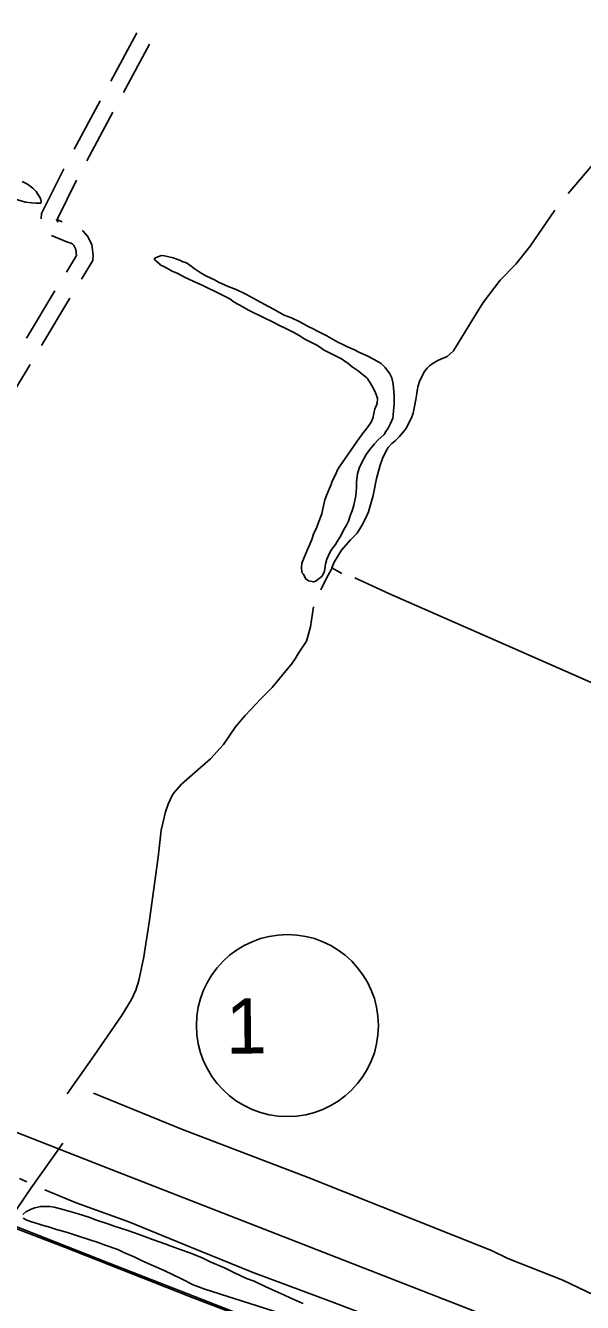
# Model space of a CAD drawing. Extents: x 3281947 to 3319794, y 715894 to 741249.
# Drawn here: x 3294621 to 3295631, y 724593 to 726907 of the extents above; entities that cross this region are included whole.
import ezdxf

# ---------------------------------------------------------------- set-up
doc = ezdxf.new("R2010")
doc.units = 0
for name, color, linetype in [('V-DTCH-CNTR', 7, 'Continuous'), ('V-RAIL-TRAK', 7, 'Continuous'), ('V-ROAD-CNTR', 7, 'Continuous'), ('V-ROAD-IDEN', 7, 'Continuous'), ('V-SITE-VEGE', 7, 'Continuous'), ('V-TOPO-SHOR', 7, 'Continuous')]:
    doc.layers.add(name, color=color, linetype=linetype)

msp = doc.modelspace()

# ---------------------------------------------------------------- linework, layer by layer
at = {"layer": 'V-DTCH-CNTR'}
msp.add_lwpolyline([(3294584.6, 724734.7), (3294604.3, 724761.8), (3294630.9, 724801.3), (3294647.3, 724824.2), (3294669.8, 724855.4), (3294688, 724881.7)], dxfattribs=at)
at = {"layer": 'V-RAIL-TRAK'}
msp.add_lwpolyline([(3295596.8, 724339.4), (3295590.1, 724342), (3295495.8, 724379), (3295404.7, 724414.1), (3295300, 724455), (3295207.5, 724491), (3295113.3, 724528.4), (3295017.6, 724565.8), (3294919.7, 724603.6), (3294791.3, 724654.3), (3294691.5, 724693.4), (3294596.8, 724729.9), (3294584.6, 724734.7)], dxfattribs=at)
at = {"layer": 'V-ROAD-CNTR'}
for p, q in [((3294775.1, 726806.1), (3294822.5, 726894.1)), ((3294798.1, 726785.6), (3294845.5, 726873.6)), ((3294708.6, 726682.9), (3294756.1, 726770.9)), ((3294731.7, 726662.3), (3294779.1, 726750.4)), ((3294622.5, 726340.4), (3294673.9, 726426.2)), ((3294649.8, 726327.6), (3294701.2, 726413.3))]:
    msp.add_line(p, q, dxfattribs=at)
for points in [[(3287528.8, 727489.4), (3288159.7, 727246.7), (3289159.6, 726857.6), (3289743.7, 726626.7), (3290210.1, 726446.4), (3290854.7, 726194.3), (3291198.3, 726062.1), (3292329.9, 725616.5), (3292874.1, 725407.4), (3293983.9, 724974.1), (3294772.1, 724664.7), (3295711.6, 724298), (3296794.9, 723876.7), (3297613.5, 723554.1), (3297991.8, 723406.1), (3298815.4, 723086.6), (3299719.3, 722731.4), (3300678.1, 722358.1)], [(3294648.8, 726557), (3294649.6, 726566.4), (3294689.9, 726647.5)], [(3294686.8, 726551.5), (3294676.5, 726555.8), (3294679, 726551.2), (3294678.5, 726553.1), (3294679, 726558.1), (3294713.2, 726626.9)], [(3294694.7, 726460.4), (3294713.2, 726490.6), (3294713.1, 726490.1), (3294711.8, 726501.6), (3294708.3, 726508.4), (3294705.8, 726511.1), (3294703.3, 726512.6), (3294697, 726514.7), (3294667.8, 726526.9)], [(3294722, 726447.5), (3294742.7, 726481.4), (3294743.2, 726491), (3294740.9, 726510.5), (3294733.1, 726525.7), (3294725, 726534.6), (3294723.4, 726535.5)], [(3294577.9, 726207.4), (3294579.7, 726210.7), (3294629.2, 726293.2)], [(3293604.8, 725293.3), (3294762.1, 724839.9), (3295753.8, 724453.1), (3296714, 724076.6), (3298094.6, 723538.7), (3299007, 723184.6), (3299321, 723061.9), (3299523.3, 722999.2), (3299701.5, 722950.5), (3299949, 722905.2), (3300134.1, 722886.4), (3300314.5, 722877.1), (3300486.9, 722878.9), (3300681.3, 722895.7), (3300871.4, 722922.7), (3301027.9, 722958.5), (3301177.9, 722998.7), (3301318.6, 723046.1), (3301415.1, 723084.5), (3301509.5, 723122.5), (3301655.6, 723193.6), (3302010.6, 723367.2), (3302498.5, 723608.3), (3302680.4, 723698.6)]]:
    msp.add_lwpolyline(points, dxfattribs=at)
at = {"layer": 'V-ROAD-IDEN'}
msp.add_circle((3295095.6, 725095), 165, dxfattribs=at)
at = {"layer": 'V-SITE-VEGE'}
for points in [[(3294614.4, 726624.7), (3294624.4, 726619.9), (3294634, 726612.7), (3294639.8, 726606.7), (3294648, 726594), (3294649.2, 726588.1), (3294648.3, 726585.2), (3294639.1, 726585.3), (3294631.9, 726585.9), (3294620.6, 726587.3), (3294593.9, 726594.7)], [(3294909.1, 726451.4), (3294896.6, 726457.9), (3294886.6, 726462.2), (3294876.6, 726467.8), (3294871.2, 726470.3), (3294865, 726473.8), (3294863.3, 726475.5), (3294857.1, 726481), (3294854.2, 726484.4), (3294856.3, 726486.5), (3294863.5, 726489.3), (3294867.3, 726490.5), (3294872.7, 726489.6), (3294888.6, 726486.5), (3294894.9, 726483.9), (3294901.6, 726481.7), (3294905.7, 726479.1), (3294912.4, 726476.9), (3294917, 726474.4), (3294921.2, 726471.4), (3294926.6, 726467.1), (3294939.4, 726458.6), (3294949, 726453), (3294963.2, 726446.5), (3294970.7, 726442.2), (3294988.2, 726434.4), (3295002.4, 726428.8), (3295020.3, 726420.2), (3295033.2, 726413.3), (3295053.2, 726402.1), (3295070.3, 726393.5), (3295089.9, 726382.4), (3295102.8, 726377.6), (3295118.3, 726370.3), (3295128.7, 726364.2), (3295134.5, 726361.2), (3295141.2, 726358.2), (3295150.3, 726353.5), (3295157.4, 726349.6), (3295168.3, 726344.4), (3295170.3, 726343.2), (3295187, 726333.7), (3295197.4, 726328.5), (3295204.5, 726324.7), (3295217, 726319.5), (3295225.3, 726315.2), (3295241.6, 726307.8), (3295251.6, 726302.7), (3295265.8, 726294.5), (3295272.8, 726287.3), (3295281.1, 726275.9), (3295284.7, 726268.7), (3295287.5, 726257.3), (3295289.4, 726237.2), (3295289.2, 726221.2), (3295287.7, 726209.1), (3295287.6, 726202)], [(3295287.6, 726202), (3295286.7, 726195.7), (3295282.8, 726186.1), (3295278.5, 726177.3), (3295274.2, 726171.5), (3295270.8, 726166.1), (3295259.8, 726155.8), (3295253.4, 726149.1), (3295244.9, 726138.7), (3295238.5, 726129.6), (3295230.3, 726115.4), (3295225.6, 726105.4), (3295222.9, 726095), (3295221, 726079.5), (3295220.9, 726069.4), (3295219.5, 726054.8), (3295218.1, 726046.4), (3295216.3, 726038), (3295213.2, 726027.6), (3295210.2, 726020.5), (3295206.3, 726009.2), (3295202.9, 726002.1), (3295197.3, 725992.5), (3295194.3, 725986.3), (3295191.2, 725980.5), (3295185.7, 725972.1), (3295182.7, 725966.7), (3295176.3, 725958.4), (3295172.4, 725952.2), (3295166.8, 725940.1), (3295164.6, 725931.3), (3295162.8, 725918.3), (3295158.4, 725909.6), (3295147.4, 725900.9), (3295143.2, 725898.9), (3295134, 725901.1), (3295129, 725904.5), (3295124.1, 725913.4), (3295122, 725916.3), (3295121.3, 725926), (3295121.8, 725932.7), (3295126.2, 725943.1), (3295131.8, 725957.7), (3295134.8, 725964.4), (3295139.6, 725976.1), (3295142.6, 725985.3), (3295148.7, 725998.2), (3295152.6, 726008.2), (3295157.8, 726022.4), (3295160, 726031.6), (3295163.2, 726047.5), (3295167.9, 726058.4), (3295174.9, 726075.5), (3295177, 726081.3), (3295183.1, 726094.2), (3295185.7, 726100.9), (3295189.5, 726106.7), (3295226.3, 726160), (3295228.4, 726162.9), (3295231.4, 726166.6), (3295235.7, 726172.8), (3295239.9, 726178.2), (3295247.2, 726188.6), (3295250.2, 726195.7), (3295254.2, 726212.5), (3295257.3, 726219.5), (3295258.6, 726222.9), (3295258.7, 726231.3), (3295256.7, 726238.4), (3295253.4, 726245.6), (3295249.7, 726252.4), (3295244.8, 726260.8), (3295242.7, 726263.8), (3295241.1, 726266.7), (3295239.4, 726268.9), (3295231.1, 726275.7), (3295224.1, 726281.2), (3295212.8, 726288.9), (3295205.8, 726294.5), (3295193.7, 726303), (3295161.2, 726319.8), (3295155.8, 726323.6), (3295148.8, 726327.9), (3295135.8, 726334.4), (3295127.1, 726339.1), (3295117.1, 726345.5), (3295107.1, 726350.7), (3295091.7, 726358.9), (3295082.5, 726363.2), (3295067.5, 726370.9), (3295054.6, 726376.9), (3295025, 726391.6), (3295014.6, 726397.6), (3294999.2, 726406.2), (3294990.9, 726412.2), (3294962.1, 726426.4), (3294952.9, 726430.7), (3294940.8, 726436.7), (3294932.5, 726440.2), (3294917.9, 726447.1), (3294909.1, 726451.4)], [(3294615.8, 724752.5), (3294621.3, 724757.5), (3294631, 724762.4), (3294637.4, 724764.9), (3294648.3, 724767.2), (3294664.7, 724767), (3294672.6, 724765.7), (3294684.3, 724763), (3294690.6, 724761.2), (3294703.1, 724757.3), (3294716.1, 724753.8), (3294735.7, 724747.6), (3294749.5, 724742.4), (3294770, 724735.9), (3294781.6, 724731.5), (3294804.2, 724724.1), (3294818.4, 724719.3), (3294838, 724712.3), (3294851, 724707.6), (3294875.2, 724698.9), (3294882.7, 724695.8), (3294902.7, 724688.9), (3294916.9, 724683.6), (3294939.5, 724674.5), (3294955.3, 724667.2), (3294981.2, 724656), (3294998.3, 724647.4), (3295021.2, 724637), (3295035, 724631.8), (3295055.4, 724622.3), (3295068.8, 724616.2), (3295090.4, 724606.7), (3295100.4, 724601.6), (3295118, 724593.8), (3295124.2, 724591.2)], [(3295137.6, 724556.2), (3294945.9, 724617.4), (3294924.6, 724625.2), (3294903.3, 724636.4), (3294872.1, 724651.5), (3294853.7, 724658.9), (3294832.4, 724668.8), (3294819.1, 724675.3), (3294799.1, 724683.9), (3294787.8, 724689.5), (3294765.3, 724696.9), (3294752.3, 724701.7), (3294716.8, 724713.5), (3294698.4, 724719.2), (3294688, 724722.3), (3294676.7, 724725.8), (3294662.1, 724730.1), (3294650.8, 724733.2), (3294643.7, 724735.8), (3294631.2, 724739.3), (3294622.8, 724742.4), (3294616.6, 724746.2)]]:
    msp.add_lwpolyline(points, dxfattribs=at)
at = {"layer": 'V-TOPO-SHOR'}
for p, q in [((3295194.4, 725914), (3295176.3, 725924.5)), ((3294622.7, 724811.6), (3294609.6, 724817.8))]:
    msp.add_line(p, q, dxfattribs=at)
for points in [[(3295604.7, 726602.8), (3295714.9, 726732.1), (3295761.8, 726792), (3295778.5, 726814.3), (3295788.2, 726831.1), (3295794.2, 726840.2), (3295805.5, 726852), (3295811.9, 726857.4), (3295825.8, 726865.7), (3295839, 726872.1)], [(3295580.5, 726572.9), (3295535.7, 726507.3), (3295510, 726474.8), (3295481.5, 726445.8), (3295450.7, 726405.5), (3295430.3, 726372), (3295396.6, 726317.6), (3295385.4, 726307.3), (3295369.8, 726300.7), (3295359.7, 726295.4), (3295353.3, 726290.6), (3295349, 726286.2), (3295344.2, 726280.4), (3295338.9, 726270.1), (3295335.3, 726262.3), (3295331.9, 726252.4), (3295331.4, 726248.9), (3295330.5, 726240.4), (3295328.7, 726229.5), (3295325.8, 726217.1), (3295323.4, 726205), (3295320.5, 726196.3), (3295310.2, 726176.4), (3295298.8, 726162.5), (3295290.9, 726154.9), (3295285, 726149.5), (3295278.5, 726142.5), (3295274.2, 726135.5), (3295267.8, 726122.6), (3295263.7, 726110.4), (3295257.1, 726086.5), (3295251.1, 726055.3), (3295242.3, 726026.1), (3295237, 726013.9), (3295230.4, 726001.4), (3295222.3, 725987.6), (3295209.8, 725975.2), (3295193.7, 725956.3), (3295180.6, 725935), (3295176.3, 725924.5)], [(3295176.3, 725924.5), (3295175.3, 725921.9), (3295166.2, 725905.7), (3295156.4, 725884.4)], [(3296135.4, 725506.5), (3295949.9, 725582.5), (3295680.6, 725701.8), (3295473.8, 725792.9), (3295280.5, 725877.6), (3295217.8, 725906.2)], [(3295142.9, 725853.9), (3295137.6, 725817.6), (3295130.2, 725791.4), (3295122, 725778.8), (3295115.8, 725769.7), (3295109.6, 725759.5), (3295103.1, 725750.2), (3295095.6, 725741.6), (3295067.8, 725707.6), (3295047.7, 725687.8), (3295019, 725656.9), (3295001.6, 725636.4), (3294979.8, 725604.3), (3294955.8, 725578.2), (3294927.4, 725553.7), (3294903.7, 725532.6), (3294890, 725517.4), (3294886.6, 725511.7), (3294879.4, 725496), (3294874.5, 725482.6), (3294866.7, 725449), (3294861.1, 725399.9), (3294845.2, 725286.2), (3294835.1, 725219.5), (3294826.1, 725176.7), (3294820.7, 725159.2), (3294812.5, 725142.4), (3294794.5, 725112.9), (3294744.8, 725040.8), (3294696.2, 724971.1)], [(3295465.9, 724687.2), (3295133.3, 724819.8), (3294905.5, 724907), (3294743.8, 724972.7)], [(3295605, 724421.7), (3295518.5, 724455.5), (3295387.7, 724511.6), (3295306.1, 724544.8), (3295180.9, 724592.7), (3295031.5, 724648), (3294918.8, 724694), (3294808.1, 724739.3), (3294712.7, 724773.7), (3294655.9, 724797.4)], [(3295677.1, 724594.5), (3295594.8, 724633.8), (3295495.2, 724673), (3295465.9, 724687.2)]]:
    msp.add_lwpolyline(points, dxfattribs=at)

# ---------------------------------------------------------------- texts
at = {"layer": 'V-ROAD-IDEN'}
msp.add_text(' 1 ', height=100, rotation=0.4943, dxfattribs=at).set_placement((3294947.2, 725043.7))

doc.saveas('drawing.dxf')
